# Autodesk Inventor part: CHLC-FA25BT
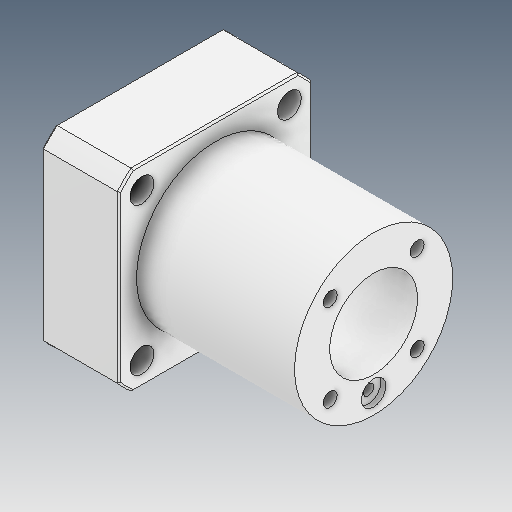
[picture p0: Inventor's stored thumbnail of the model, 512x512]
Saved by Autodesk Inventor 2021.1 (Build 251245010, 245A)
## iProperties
Created: 2021-05
Part Number: CHLC-FA25BT
Material: Ogólny
Document SubType Name: Modeling
Designer: user
Density: 1 g/cm^3
Appearance: Domyślna
Author: user
Revision Number: ÈÎºÎ
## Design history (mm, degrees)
feature "ÊäÈë1"
node "Bryła1"
